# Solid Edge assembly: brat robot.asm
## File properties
Author: User
Template: Iso Metric Assembly.asm
Last saved by: User
Revision: 7
Application: Solid Edge
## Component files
sina.par
stalp.par
brat orizontal.par
gheara.par
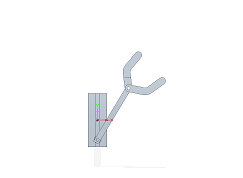
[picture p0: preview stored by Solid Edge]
